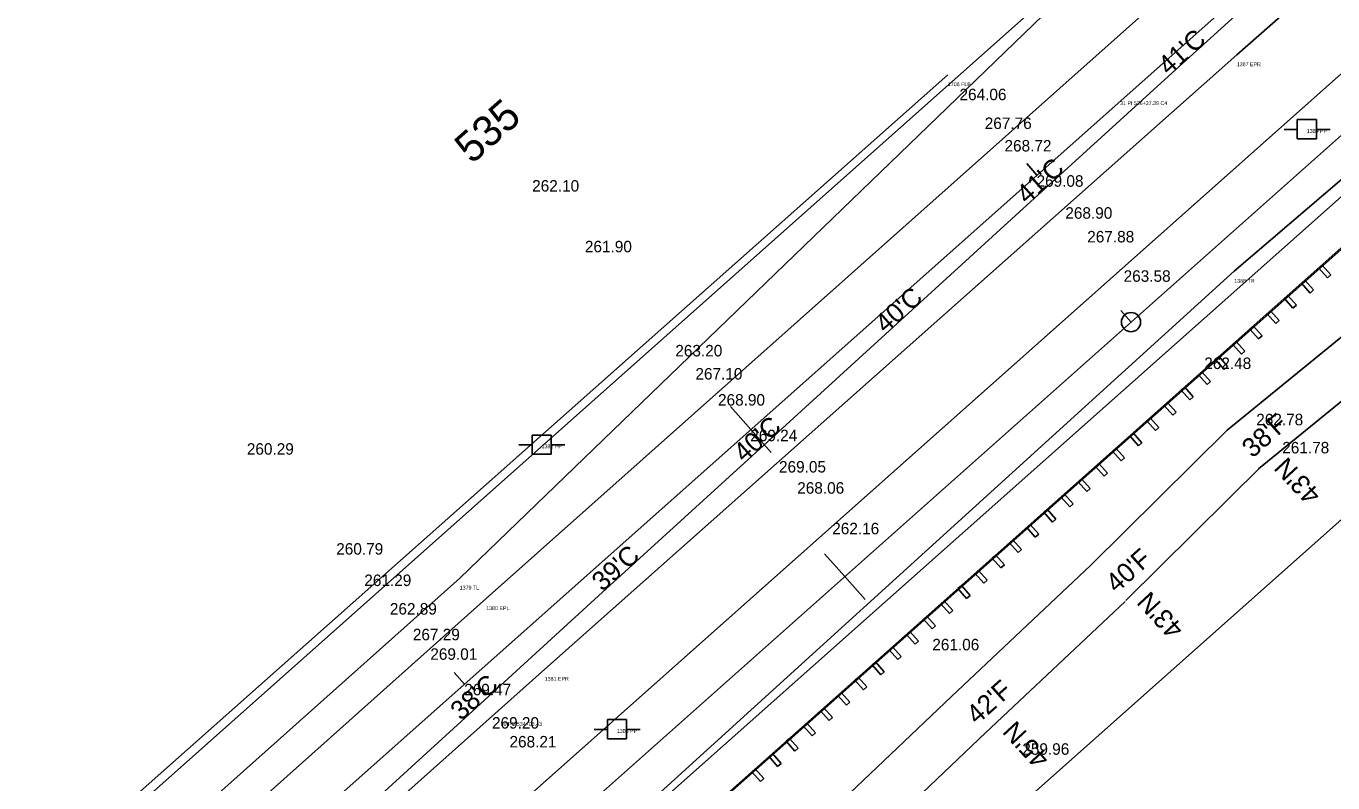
# Model space of a CAD drawing. Extents: x 49683 to 58852, y 49525 to 54803.
# Drawn here: x 54598 to 54939.2, y 52584.3 to 52781.8 of the extents above; entities that cross this region are included whole.
import ezdxf

# ---------------------------------------------------------------- set-up
doc = ezdxf.new("R2010")
doc.units = 0
for name, color, linetype in [('Level 1', 7, 'Continuous'), ('Level 11', 7, 'Continuous'), ('Level 13', 7, 'Continuous'), ('Level 18', 7, 'Continuous'), ('Level 19', 7, 'Continuous'), ('Level 20', 7, 'Continuous'), ('Level 21', 7, 'Continuous'), ('Level 27', 7, 'Continuous'), ('Level 3', 7, 'Continuous'), ('Level 32', 7, 'Continuous'), ('Level 33', 7, 'Continuous'), ('Level 48', 7, 'Continuous'), ('Level 51', 7, 'Continuous'), ('Level 53', 7, 'Continuous'), ('Level 58', 7, 'Continuous'), ('Level 59', 7, 'Continuous'), ('Level 61', 7, 'Continuous'), ('Level 8', 7, 'Continuous'), ('Level 9', 7, 'Continuous')]:
    doc.layers.add(name, color=color, linetype=linetype)

# ---------------------------------------------------------------- blocks, each defined once
blk = doc.blocks.new('PP')
at = {"layer": 'Level 9'}
for p, q in [((2.53, 2.45), (-2.47, 2.45)), ((-2.47, 2.45), (-2.47, -2.55)), ((2.53, -2.55), (2.53, 2.45)), ((-5.91, -0.11), (-2.44, -0.11)), ((-2.47, -2.55), (2.53, -2.55)), ((2.45, -0.11), (6.09, -0.11))]:
    blk.add_line(p, q, dxfattribs=at)

msp = doc.modelspace()

# ---------------------------------------------------------------- linework, layer by layer
at = {"layer": 'Level 1'}
for p, q in [((52544.81, 50683.3), (55534.58, 53340.86)), ((54861.91, 52742.94), (54859.26, 52745.93)), ((54787.17, 52676.5), (54781.86, 52682.48)), ((54792.49, 52670.52), (54787.17, 52676.5)), ((54712.43, 52610.06), (54709.77, 52613.05))]:
    msp.add_line(p, q, dxfattribs=at)
at = {"layer": 'Level 11'}
for p, q in [((54913.43, 52717.81), (55106.73, 52883.65)), ((54711.21, 52637.72), (54944.99, 52863.38)), ((54757.25, 52576.08), (54913.43, 52717.81)), ((54324.2, 52292.62), (54711.21, 52637.72))]:
    msp.add_line(p, q, dxfattribs=at)
at = {"layer": 'Level 13'}
for p, q in [((55279.53, 53070), (53969.03, 51905.11)), ((54971.79, 52884.76), (53925.18, 51954.44))]:
    msp.add_line(p, q, dxfattribs=at)
at = {"layer": 'Level 18'}
for p, q in [((54896.29, 52768.76), (54933.3, 52802.37)), ((54859.29, 52735.12), (54896.29, 52768.76)), ((54822.37, 52701.4), (54859.29, 52735.12)), ((54911.54, 52676.33), (54950.34, 52707.95)), ((54785.43, 52667.69), (54822.37, 52701.4)), ((54919.76, 52666.26), (54958.55, 52697.87)), ((54875.99, 52641.07), (54911.54, 52676.33)), ((54748.46, 52634.02), (54785.43, 52667.69)), ((54885.14, 52631.84), (54920.7, 52667.1)), ((54839.6, 52606.76), (54875.99, 52641.07)), ((54711.55, 52600.29), (54748.46, 52634.02)), ((54848.51, 52597.3), (54884.91, 52631.61)), ((54803.29, 52572.34), (54839.6, 52606.76)), ((54674.65, 52566.54), (54711.55, 52600.29)), ((54812.22, 52562.88), (54848.51, 52597.3))]:
    msp.add_line(p, q, dxfattribs=at)
at = {"layer": 'Level 19'}
for p, q in [((54181.77, 52078.16), (56150.85, 53828.45)), ((54886.46, 52704.55), (54883.8, 52707.54)), ((54811.72, 52638.11), (54806.41, 52644.09)), ((54811.72, 52638.11), (54817.04, 52632.14))]:
    msp.add_line(p, q, dxfattribs=at)
msp.add_circle((54886.46, 52704.55), 2.5, dxfattribs=at)
at = {"layer": 'Level 20'}
for p, q in [((54173.8, 52087.13), (55269.45, 53061.04)), ((54189.74, 52069.19), (55278.86, 53037.3))]:
    msp.add_line(p, q, dxfattribs=at)
at = {"layer": 'Level 27'}
for p, q in [((54196.38, 52061.72), (54970.77, 52750.06)), ((54196.55, 52061.53), (54970.94, 52749.87)), ((54935.46, 52718.67), (54936.34, 52719.45)), ((54937.72, 52716.13), (54935.46, 52718.67)), ((54936.34, 52719.45), (54938.6, 52716.91)), ((54938.6, 52716.91), (54937.72, 52716.13)), ((54930.97, 52714.68), (54931.86, 52715.47)), ((54933.23, 52712.14), (54930.97, 52714.68)), ((54931.86, 52715.47), (54934.12, 52712.93)), ((54926.49, 52710.7), (54927.37, 52711.48)), ((54928.75, 52708.15), (54926.49, 52710.7)), ((54927.37, 52711.48), (54929.63, 52708.94)), ((54934.12, 52712.93), (54933.23, 52712.14)), ((54922.01, 52706.71), (54922.89, 52707.5)), ((54924.26, 52704.17), (54922.01, 52706.71)), ((54922.89, 52707.5), (54925.15, 52704.95)), ((54929.63, 52708.94), (54928.75, 52708.15)), ((54917.52, 52702.72), (54918.4, 52703.51)), ((54918.4, 52703.51), (54920.66, 52700.97)), ((54925.15, 52704.95), (54924.26, 52704.17)), ((54919.78, 52700.18), (54917.52, 52702.72)), ((54920.66, 52700.97), (54919.78, 52700.18)), ((54913.04, 52698.74), (54913.92, 52699.52)), ((54915.3, 52696.2), (54913.04, 52698.74)), ((54913.92, 52699.52), (54916.18, 52696.98)), ((54916.18, 52696.98), (54915.3, 52696.2)), ((54908.55, 52694.75), (54909.44, 52695.54)), ((54910.81, 52692.21), (54908.55, 52694.75)), ((54909.44, 52695.54), (54911.69, 52693)), ((54911.69, 52693), (54910.81, 52692.21)), ((54904.07, 52690.77), (54904.95, 52691.55)), ((54906.33, 52688.22), (54904.07, 52690.77)), ((54904.95, 52691.55), (54907.21, 52689.01)), ((54899.58, 52686.78), (54900.47, 52687.56)), ((54901.84, 52684.24), (54899.58, 52686.78)), ((54900.47, 52687.56), (54902.73, 52685.02)), ((54907.21, 52689.01), (54906.33, 52688.22)), ((54895.1, 52682.79), (54895.98, 52683.58)), ((54897.36, 52680.25), (54895.1, 52682.79)), ((54895.98, 52683.58), (54898.24, 52681.04)), ((54902.73, 52685.02), (54901.84, 52684.24)), ((54890.61, 52678.81), (54891.5, 52679.59)), ((54891.5, 52679.59), (54893.76, 52677.05)), ((54898.24, 52681.04), (54897.36, 52680.25)), ((54892.87, 52676.27), (54890.61, 52678.81)), ((54893.76, 52677.05), (54892.87, 52676.27)), ((54886.13, 52674.82), (54887.01, 52675.61)), ((54888.39, 52672.28), (54886.13, 52674.82)), ((54887.01, 52675.61), (54889.27, 52673.06)), ((54889.27, 52673.06), (54888.39, 52672.28)), ((54881.65, 52670.83), (54882.53, 52671.62)), ((54883.9, 52668.29), (54881.65, 52670.83)), ((54882.53, 52671.62), (54884.79, 52669.08)), ((54884.79, 52669.08), (54883.9, 52668.29)), ((54877.16, 52666.85), (54878.04, 52667.63)), ((54879.42, 52664.31), (54877.16, 52666.85)), ((54878.04, 52667.63), (54880.3, 52665.09)), ((54872.68, 52662.86), (54873.56, 52663.65)), ((54874.93, 52660.32), (54872.68, 52662.86)), ((54873.56, 52663.65), (54875.82, 52661.11)), ((54880.3, 52665.09), (54879.42, 52664.31)), ((54868.19, 52658.88), (54869.08, 52659.66)), ((54870.45, 52656.33), (54868.19, 52658.88)), ((54869.08, 52659.66), (54871.33, 52657.12)), ((54875.82, 52661.11), (54874.93, 52660.32)), ((54863.71, 52654.89), (54864.59, 52655.68)), ((54864.59, 52655.68), (54866.85, 52653.13)), ((54871.33, 52657.12), (54870.45, 52656.33)), ((54865.97, 52652.35), (54863.71, 52654.89)), ((54866.85, 52653.13), (54865.97, 52652.35)), ((54859.22, 52650.9), (54860.11, 52651.69)), ((54861.48, 52648.36), (54859.22, 52650.9)), ((54860.11, 52651.69), (54862.37, 52649.15)), ((54862.37, 52649.15), (54861.48, 52648.36)), ((54854.74, 52646.92), (54855.62, 52647.7)), ((54857, 52644.38), (54854.74, 52646.92)), ((54855.62, 52647.7), (54857.88, 52645.16)), ((54850.25, 52642.93), (54851.14, 52643.72)), ((54852.51, 52640.39), (54850.25, 52642.93)), ((54851.14, 52643.72), (54853.4, 52641.18)), ((54857.88, 52645.16), (54857, 52644.38)), ((54845.77, 52638.95), (54846.65, 52639.73)), ((54848.03, 52636.4), (54845.77, 52638.95)), ((54846.65, 52639.73), (54848.91, 52637.19)), ((54853.4, 52641.18), (54852.51, 52640.39)), ((54841.29, 52634.96), (54842.17, 52635.74)), ((54843.54, 52632.42), (54841.29, 52634.96)), ((54842.17, 52635.74), (54844.43, 52633.2)), ((54848.91, 52637.19), (54848.03, 52636.4)), ((54836.8, 52630.97), (54837.68, 52631.76)), ((54837.68, 52631.76), (54839.94, 52629.22)), ((54844.43, 52633.2), (54843.54, 52632.42)), ((54839.06, 52628.43), (54836.8, 52630.97)), ((54839.94, 52629.22), (54839.06, 52628.43)), ((54832.32, 52626.99), (54833.2, 52627.77)), ((54834.57, 52624.45), (54832.32, 52626.99)), ((54833.2, 52627.77), (54835.46, 52625.23)), ((54835.46, 52625.23), (54834.57, 52624.45)), ((54827.83, 52623), (54828.72, 52623.79)), ((54830.09, 52620.46), (54827.83, 52623)), ((54828.72, 52623.79), (54830.97, 52621.24)), ((54823.35, 52619.01), (54824.23, 52619.8)), ((54825.61, 52616.47), (54823.35, 52619.01)), ((54824.23, 52619.8), (54826.49, 52617.26)), ((54830.97, 52621.24), (54830.09, 52620.46)), ((54818.86, 52615.03), (54819.75, 52615.81)), ((54821.12, 52612.49), (54818.86, 52615.03)), ((54819.75, 52615.81), (54822, 52613.27)), ((54826.49, 52617.26), (54825.61, 52616.47)), ((54814.38, 52611.04), (54815.26, 52611.83)), ((54815.26, 52611.83), (54817.52, 52609.29)), ((54822, 52613.27), (54821.12, 52612.49)), ((54809.89, 52607.06), (54810.78, 52607.84)), ((54810.78, 52607.84), (54813.04, 52605.3)), ((54816.64, 52608.5), (54814.38, 52611.04)), ((54817.52, 52609.29), (54816.64, 52608.5)), ((54812.15, 52604.51), (54809.89, 52607.06)), ((54813.04, 52605.3), (54812.15, 52604.51)), ((54805.41, 52603.07), (54806.29, 52603.85)), ((54807.67, 52600.53), (54805.41, 52603.07)), ((54806.29, 52603.85), (54808.55, 52601.31)), ((54808.55, 52601.31), (54807.67, 52600.53)), ((54800.93, 52599.08), (54801.81, 52599.87)), ((54803.18, 52596.54), (54800.93, 52599.08)), ((54801.81, 52599.87), (54804.07, 52597.33)), ((54796.44, 52595.1), (54797.32, 52595.88)), ((54798.7, 52592.56), (54796.44, 52595.1)), ((54797.32, 52595.88), (54799.58, 52593.34)), ((54804.07, 52597.33), (54803.18, 52596.54)), ((54791.96, 52591.11), (54792.84, 52591.9)), ((54794.21, 52588.57), (54791.96, 52591.11)), ((54792.84, 52591.9), (54795.1, 52589.35)), ((54799.58, 52593.34), (54798.7, 52592.56)), ((54787.47, 52587.13), (54788.36, 52587.91)), ((54788.36, 52587.91), (54790.61, 52585.37)), ((54795.1, 52589.35), (54794.21, 52588.57)), ((54789.73, 52584.58), (54787.47, 52587.13)), ((54790.61, 52585.37), (54789.73, 52584.58))]:
    msp.add_line(p, q, dxfattribs=at)
at = {"layer": 'Level 3'}
for p, q in [((54914.07, 52774.35), (54968.8, 52822.44)), ((54718.13, 52632.37), (54897.27, 52791.82)), ((54733.4, 52613.92), (54914.07, 52774.35)), ((54524.1, 52459.42), (54718.13, 52632.37)), ((54540.49, 52442.07), (54733.4, 52613.92))]:
    msp.add_line(p, q, dxfattribs=at)
at = {"layer": 'Level 33'}
msp.add_line((54231.59, 52022.1), (55608.96, 53246.42), dxfattribs=at)
at = {"layer": 'Level 8'}
msp.add_line((54015.78, 52039), (54838.64, 52769.14), dxfattribs=at)

# ---------------------------------------------------------------- block references
at = {"layer": 'Level 9'}
for p in [(54932.35, 52754.96), (54732.57, 52672.62), (54752.23, 52598.31)]:
    msp.add_blockref('PP', p, dxfattribs=at)

# ---------------------------------------------------------------- texts
at = {"layer": 'Level 21'}
msp.add_text('535', height=8, rotation=41.6333, dxfattribs=at).set_placement((54714.39, 52745.6))
at = {"layer": 'Level 32'}
for s, p in [('264.06', (54841.68, 52762.48)), ('267.76', (54848.27, 52754.96)), ('268.72', (54853.43, 52749.09)), ('262.10', (54730.12, 52738.62)), ('269.08', (54861.79, 52739.89)), ('268.90', (54869.31, 52731.54)), ('267.88', (54875.03, 52725.35)), ('261.90', (54743.89, 52722.77)), ('263.58', (54884.53, 52715.07)), ('263.20', (54767.49, 52695.59)), ('262.48', (54905.58, 52692.3)), ('267.10', (54772.74, 52689.55)), ('268.90', (54778.64, 52682.75)), ('262.78', (54919.15, 52677.61)), ('269.24', (54787.07, 52673.45)), ('260.29', (54655.63, 52669.93)), ('261.78', (54925.94, 52670.27)), ('269.05', (54794.56, 52665.27)), ('268.06', (54799.32, 52659.75)), ('262.16', (54808.46, 52649.15)), ('260.79', (54678.97, 52643.84)), ('261.29', (54686.3, 52635.64)), ('262.89', (54692.97, 52628.19)), ('267.29', (54698.97, 52621.48)), ('261.06', (54834.58, 52618.85)), ('269.01', (54703.53, 52616.38)), ('269.47', (54712.37, 52607.11)), ('269.20', (54719.64, 52598.42)), ('268.21', (54724.2, 52593.5)), ('259.96', (54858.08, 52591.59))]:
    msp.add_text(s, height=3, dxfattribs=at).set_placement(p)
at = {"layer": 'Level 48'}
for s, rotation, p in [("41'C", 41.6334, (54896.29, 52768.76)), ("41'C", 41.6334, (54859.29, 52735.12)), ("40'C", 41.6334, (54822.37, 52701.4)), ("40'C", 41.6334, (54785.43, 52667.69)), ("38'F", 41.6334, (54918.19, 52668.86)), ("43'N", 132.8528, (54936.35, 52659.72)), ("39'C", 41.6334, (54748.46, 52634.02)), ("40'F", 41.6334, (54882.63, 52633.6)), ("43'N", 132.8528, (54900.54, 52624.66)), ("38'C", 41.6334, (54711.55, 52600.29)), ("42'F", 41.6334, (54846.24, 52599.28)), ("45'N", 132.8528, (54865.5, 52590.88))]:
    msp.add_text(s, height=5, rotation=rotation, dxfattribs=at).set_placement(p)
at = {"layer": 'Level 51'}
for s, p in [('31 PI 536+37.39 C4', (54883.6, 52761.22)), ('30 PC 534+08.43', (54721.89, 52599.13))]:
    msp.add_text(s, height=1, dxfattribs=at).set_placement(p)
at = {"layer": 'Level 53'}
for s, p in [('1387 EPR', (54914.07, 52771.35)), ('1380 EPL', (54718.13, 52629.37)), ('1381 EPR', (54733.4, 52610.92))]:
    msp.add_text(s, height=1, dxfattribs=at).set_placement(p)
at = {"layer": 'Level 58'}
msp.add_text('1706 FLB', height=1, dxfattribs=at).set_placement((54838.64, 52766.15))
at = {"layer": 'Level 59'}
for s, p in [('1389 PP', (54932.35, 52753.96)), ('1382 PP', (54732.57, 52671.62)), ('1383 PP', (54752.23, 52597.31))]:
    msp.add_text(s, height=1, dxfattribs=at).set_placement(p)
at = {"layer": 'Level 61'}
for s, p in [('1388 TR', (54913.43, 52714.81)), ('1379 TL', (54711.21, 52634.72))]:
    msp.add_text(s, height=1, dxfattribs=at).set_placement(p)

doc.saveas('drawing.dxf')
